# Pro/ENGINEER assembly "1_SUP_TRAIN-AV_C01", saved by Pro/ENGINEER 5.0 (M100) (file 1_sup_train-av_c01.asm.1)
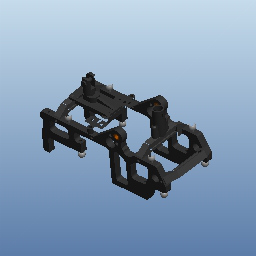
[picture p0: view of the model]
Units: millimeter Newton Second (mmNs); MM, TONNE, HOURS

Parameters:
  MC_INTF = "09/27/2011 270"

Other components: SUP_TRAIN-AV_C01, 80464502-CHAPE_ANC_AMORT_AV_C01, 80350802-PONT_AV_C01, 80350802-PONT_AV_C01, 80605300-SUPPORT_SERVO_C01, 80350802-PONT_AV_C01, SUPPORT_CAROSSERIE_C01, AXE_AMORT_C02, 80351000-SUP_AM_AV_RACING_C01, SUP_TRAIN-AV_C01

Other named items: A-DROITE, A-DESSUS, A-FACE, A-R0, ACS0, ACS1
